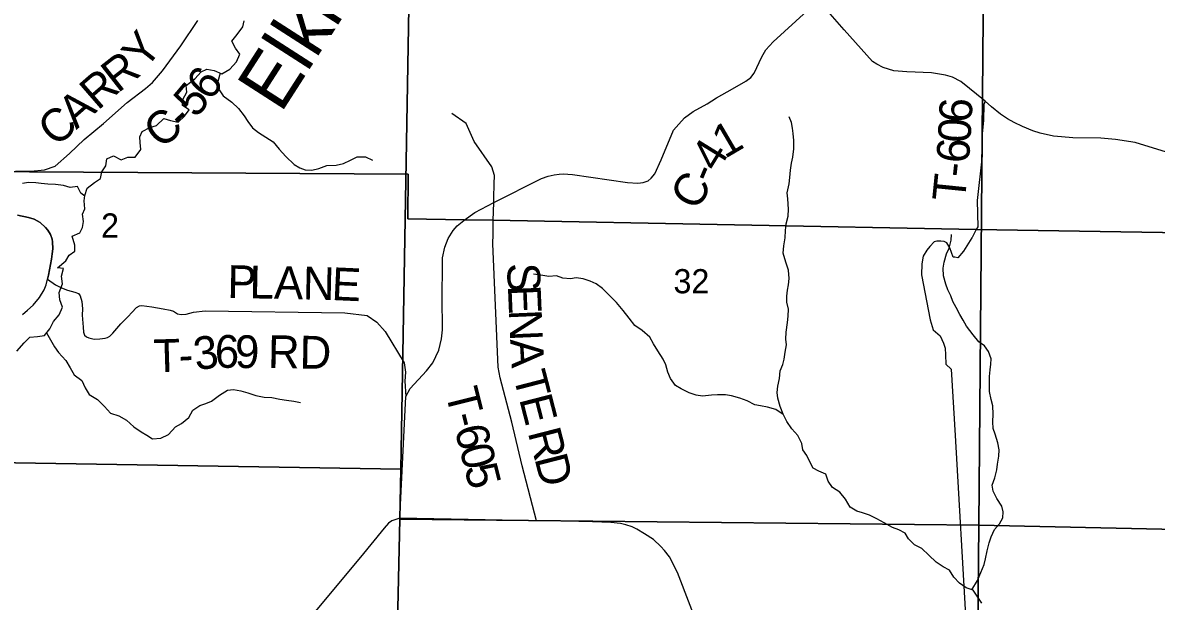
# Model space of a CAD drawing. Extents: x -3.6 to 34, y 0 to 32.8.
# Drawn here: x -0.41 to 1.556, y 29.85 to 30.853 of the extents above; entities that cross this region are included whole.
import ezdxf

# ---------------------------------------------------------------- set-up
doc = ezdxf.new("R2010")
doc.units = 0
for name, color, linetype in [('GM_X_Corporation', 7, 'Continuous'), ('GM_X_County_Road', 7, 'Continuous'), ('GM_X_County_Road_Text', 7, 'Continuous'), ('GM_X_Minor_River', 7, 'Continuous'), ('GM_X_Minor_River_Text', 7, 'Continuous'), ('GM_X_Section_Text', 7, 'Continuous'), ('GM_X_State_Route', 7, 'Continuous'), ('GM_X_Township_Road', 7, 'Continuous'), ('GM_X_Township_Road_Text', 7, 'Continuous')]:
    doc.layers.add(name, color=color, linetype=linetype)

msp = doc.modelspace()

# ---------------------------------------------------------------- linework, layer by layer
at = {"layer": 'GM_X_Corporation'}
for points in [[(3.1705, 30.458), (3.1705, 32.8429), (-3.6295, 32.8429), (-3.6295, 30.6462), (-3.5736, 30.6453), (-2.8007, 30.6338), (-2.7027, 30.634), (-2.3541, 30.6318), (-0.5034, 30.5954), (-0.453, 30.5952), (-0.398, 30.5946), (0.2583, 30.5905), (0.2578, 30.5133), (0.3556, 30.5115), (0.4055, 30.5105), (1.2437, 30.4948), (1.7819, 30.4857), (3.0419, 30.4594)], [(-0.7569, 31.1125), (0.2635, 31.0982), (0.262, 31.0128), (0.2459, 30.0789), (-0.7755, 30.0957)], [(0.262, 31.0128), (1.2573, 30.9978), (1.2483, 29.9822), (0.244, 29.9924), (0.2459, 30.0789)], [(1.2573, 30.9978), (2.27, 30.9827), (2.2535, 29.9602), (1.2483, 29.9822)], [(-0.7755, 30.0957), (0.2459, 30.0789), (0.244, 29.9924), (0.223, 29.0627), (-0.7627, 29.0764), (-0.7893, 29.0771)], [(1.2483, 29.9822), (1.2386, 28.9647), (0.2524, 28.9828), (0.2209, 28.9831), (0.223, 29.0627), (0.244, 29.9924)], [(2.2535, 29.9602), (2.2411, 28.9502), (1.4051, 28.9619), (1.2386, 28.9647), (1.2483, 29.9822)]]:
    msp.add_lwpolyline(points, close=True, dxfattribs=at)
msp.add_lwpolyline([(-2.8635, 26.0429), (2.3706, 26.0429), (2.3712, 26.0804), (2.3716, 26.1248), (2.3732, 26.2253), (2.3789, 26.6097), (2.3911, 27.5117), (2.3952, 27.9336), (2.3997, 28.282), (2.4082, 28.9473), (2.5416, 28.945), (2.5837, 28.9442), (2.8343, 28.9397), (3.1705, 28.9337), (3.1705, 30.458), (3.0419, 30.4594), (1.7819, 30.4857), (1.2437, 30.4948), (0.4055, 30.5105), (0.3556, 30.5115), (0.2578, 30.5133), (0.2583, 30.5905), (-0.398, 30.5946), (-0.453, 30.5952)], dxfattribs=at)
at = {"layer": 'GM_X_County_Road'}
for points in [[(0.3549, 30.5103), (0.3558, 30.5109), (0.3742, 30.5239), (0.4072, 30.5411), (0.4898, 30.5832), (0.5014, 30.5872), (0.5118, 30.5894), (0.5207, 30.5907), (0.5274, 30.5909), (0.5436, 30.5902), (0.639, 30.5761), (0.6567, 30.5751), (0.666, 30.5758), (0.6747, 30.579), (0.6801, 30.5836), (0.6861, 30.5913), (0.6971, 30.6153), (0.7189, 30.667), (0.7279, 30.6773), (0.7381, 30.6883), (0.7526, 30.6993), (0.777, 30.7127), (0.7935, 30.723), (0.821, 30.7385), (0.8441, 30.7516), (0.8528, 30.7582), (0.8588, 30.7657), (0.8719, 30.7941), (0.8787, 30.8061), (0.8918, 30.82), (0.9701, 30.8915)], [(-0.4222, 30.5962), (-0.3959, 30.5957), (-0.372, 30.5979), (-0.354, 30.6042), (-0.3288, 30.6261), (-0.3034, 30.6505), (-0.2697, 30.6781), (-0.229, 30.7149), (-0.1968, 30.7392), (-0.185, 30.7494), (-0.1673, 30.7695), (-0.136, 30.813), (-0.1061, 30.8567)], [(-0.3669, 30.4082), (-0.3655, 30.4152), (-0.3601, 30.4429), (-0.3589, 30.4521), (-0.358, 30.4613), (-0.3583, 30.473), (-0.359, 30.4776), (-0.3619, 30.4858), (-0.3664, 30.4937), (-0.3704, 30.498), (-0.3799, 30.5066), (-0.3903, 30.5123), (-0.4, 30.5155), (-0.4192, 30.5192)], [(0.2438, 29.994), (0.2545, 30.2049), (0.262, 30.219), (0.2905, 30.2496), (0.3013, 30.2633), (0.312, 30.2856), (0.3163, 30.3048), (0.3181, 30.3207), (0.3174, 30.3775), (0.3178, 30.4318), (0.3179, 30.4455), (0.3222, 30.4639), (0.3279, 30.4788), (0.3368, 30.4927), (0.3434, 30.5011), (0.3549, 30.5103)], [(-0.4105, 30.3472), (-0.4016, 30.3547), (-0.3918, 30.3635), (-0.3807, 30.3764), (-0.3727, 30.3901), (-0.3693, 30.3984), (-0.3669, 30.4082)], [(0.7696, 29.7854), (0.7256, 29.9001), (0.7116, 29.9268), (0.7034, 29.938), (0.697, 29.9451), (0.684, 29.9569), (0.6687, 29.967), (0.6554, 29.9748), (0.647, 29.9789), (0.6359, 29.9827), (0.6266, 29.9847), (0.6101, 29.9864), (0.5785, 29.9879), (0.5308, 29.9886), (0.481, 29.9897), (0.2438, 29.994), (0.2303, 29.9894), (0.2242, 29.9853), (0.2171, 29.9768), (0.1758, 29.9267), (0.0971, 29.8323)]]:
    msp.add_lwpolyline(points, dxfattribs=at)
at = {"layer": 'GM_X_Minor_River'}
for points in [[(-0.0779, 30.7703), (-0.0646, 30.7645), (-0.0507, 30.7727), (-0.0392, 30.7854), (-0.0337, 30.7987), (-0.0407, 30.8092), (-0.0473, 30.8209), (-0.038, 30.8324), (-0.028, 30.8458), (-0.0259, 30.8561)], [(-0.4201, 30.2834), (-0.4075, 30.298), (-0.3974, 30.308), (-0.3846, 30.309), (-0.3721, 30.3107), (-0.3632, 30.3226), (-0.3566, 30.3352), (-0.3469, 30.3464), (-0.3411, 30.3601), (-0.3458, 30.3725), (-0.3468, 30.3854), (-0.3409, 30.4003), (-0.343, 30.4139), (-0.3394, 30.4269), (-0.3497, 30.4279), (-0.3355, 30.4402), (-0.3296, 30.4502), (-0.3195, 30.4572), (-0.3196, 30.4674), (-0.324, 30.4833), (-0.3109, 30.4888), (-0.3065, 30.4983), (-0.3044, 30.5082), (-0.3064, 30.5211), (-0.3024, 30.5306), (-0.3034, 30.5443), (-0.302, 30.5538), (-0.2981, 30.5663), (-0.2857, 30.576), (-0.2749, 30.583), (-0.2728, 30.5948), (-0.2661, 30.6051), (-0.2644, 30.6173), (-0.2524, 30.6224), (-0.2394, 30.6154), (-0.2277, 30.6198), (-0.2152, 30.6199), (-0.2052, 30.6334), (-0.2062, 30.6455), (-0.2071, 30.655), (-0.2031, 30.6645), (-0.1895, 30.6715), (-0.1779, 30.6751), (-0.1652, 30.6871), (-0.1538, 30.6838), (-0.1405, 30.6806), (-0.1293, 30.691), (-0.1215, 30.7022), (-0.1326, 30.7096), (-0.1324, 30.7202), (-0.1254, 30.7325), (-0.1263, 30.7442), (-0.1114, 30.7558), (-0.1006, 30.7677), (-0.0908, 30.7728), (-0.0779, 30.7703)], [(-0.0676, 30.7658), (-0.0716, 30.7511), (-0.0702, 30.7386), (-0.0625, 30.7266), (-0.0472, 30.7154), (-0.0357, 30.7042), (-0.026, 30.6915), (-0.0198, 30.6817), (-0.0117, 30.6708), (-0.0013, 30.6627), (0.0246, 30.6464), (0.035, 30.634), (0.0466, 30.6209), (0.0608, 30.6071), (0.0704, 30.6012), (0.0799, 30.5983), (0.0916, 30.5977), (0.1037, 30.6005), (0.1176, 30.6057), (0.1335, 30.6063), (0.1463, 30.6091), (0.1587, 30.615), (0.17, 30.6205), (0.1843, 30.6207), (0.1969, 30.6149)], [(0.914, 30.3163), (0.9164, 30.3334), (0.9178, 30.3444), (0.9183, 30.3566), (0.9155, 30.3686), (0.9153, 30.3789), (0.9163, 30.3891), (0.9184, 30.3987), (0.9194, 30.4097), (0.918, 30.4241), (0.9137, 30.438), (0.9089, 30.4535), (0.9102, 30.466), (0.9127, 30.4801), (0.9132, 30.4926), (0.9142, 30.5044), (0.9174, 30.5177), (0.9183, 30.5299), (0.9173, 30.5477), (0.916, 30.5583), (0.9192, 30.5735), (0.9205, 30.5849), (0.9218, 30.5975), (0.9232, 30.6096), (0.9256, 30.6199), (0.9277, 30.6343), (0.9275, 30.6488), (0.9262, 30.6609), (0.9253, 30.6703), (0.9232, 30.6802), (0.9193, 30.69)], [(-0.3022, 30.5525), (-0.3093, 30.5578), (-0.3151, 30.5691), (-0.3276, 30.5674), (-0.3394, 30.571), (-0.353, 30.5727), (-0.3663, 30.5733), (-0.378, 30.5742), (-0.3875, 30.5752), (-0.4, 30.5762), (-0.4106, 30.5741)], [(1.236, 29.87), (1.246, 29.8859), (1.2519, 29.9), (1.2577, 29.9138), (1.2598, 29.9233), (1.263, 29.9374), (1.2662, 29.9511), (1.2698, 29.9617), (1.2753, 29.9743), (1.2843, 29.9843), (1.2898, 29.9947), (1.2907, 30.0053), (1.2883, 30.0151), (1.2798, 30.0279), (1.2732, 30.0407), (1.2715, 30.0513), (1.2762, 30.0639), (1.2798, 30.0776), (1.2808, 30.0878), (1.2832, 30.1015), (1.2838, 30.1125), (1.2814, 30.1246), (1.2766, 30.1397), (1.2734, 30.1495), (1.2728, 30.1613), (1.273, 30.1742), (1.2728, 30.189), (1.27, 30.1996), (1.2671, 30.2136), (1.2666, 30.2261), (1.2667, 30.2397), (1.2681, 30.2511), (1.2691, 30.261), (1.2697, 30.2705), (1.2649, 30.2829), (1.2584, 30.2927), (1.2484, 30.2998), (1.2388, 30.3121), (1.2268, 30.3271), (1.2213, 30.3373), (1.2155, 30.3474), (1.2089, 30.3591), (1.2031, 30.3696), (1.1995, 30.3794), (1.1948, 30.39), (1.1909, 30.3998), (1.1869, 30.4141), (1.1867, 30.4278), (1.1884, 30.438), (1.192, 30.4521), (1.1967, 30.4621), (1.2003, 30.4758), (1.2009, 30.486)], [(0.9092, 30.1739), (0.896, 30.1825), (0.882, 30.1865), (0.8698, 30.1889), (0.8596, 30.1903), (0.8466, 30.1973), (0.8336, 30.2024), (0.8196, 30.2064), (0.809, 30.2077), (0.795, 30.2079), (0.7848, 30.2074), (0.7693, 30.2056), (0.7583, 30.2073), (0.7457, 30.2113), (0.732, 30.2183), (0.7224, 30.2242), (0.7136, 30.2362), (0.7088, 30.2475), (0.7052, 30.26), (0.7009, 30.2698), (0.6913, 30.2841), (0.6843, 30.2961), (0.6776, 30.3077), (0.6642, 30.3197), (0.6516, 30.3282), (0.6416, 30.3406), (0.6315, 30.3541), (0.6196, 30.3679), (0.6088, 30.3788), (0.5954, 30.3922), (0.5847, 30.4004), (0.5744, 30.4052), (0.5618, 30.4091), (0.5501, 30.4109), (0.5403, 30.4088), (0.527, 30.4101), (0.516, 30.4141), (0.5023, 30.4132), (0.4887, 30.4152), (0.4762, 30.4173)], [(-0.3687, 30.3153), (-0.3548, 30.2912), (-0.3482, 30.2815), (-0.3355, 30.2673), (-0.3277, 30.2545), (-0.3207, 30.2428), (-0.3077, 30.2328), (-0.3015, 30.22), (-0.2949, 30.2083), (-0.2803, 30.1998), (-0.2684, 30.1879), (-0.258, 30.1763), (-0.2436, 30.1716), (-0.2302, 30.1642), (-0.2172, 30.1526), (-0.2046, 30.1437), (-0.195, 30.1378), (-0.1847, 30.1319), (-0.1703, 30.1325), (-0.1572, 30.1391), (-0.1449, 30.1522), (-0.1348, 30.1581), (-0.1221, 30.1689), (-0.1147, 30.1815), (-0.1027, 30.1893), (-0.0925, 30.1928), (-0.0828, 30.1968), (-0.0689, 30.2072), (-0.0551, 30.2162), (-0.0445, 30.2171), (-0.0316, 30.2146), (-0.0198, 30.2114), (-0.0057, 30.2067), (0.0087, 30.2039), (0.022, 30.2033), (0.036, 30.2005), (0.0474, 30.1988), (0.0603, 30.1971), (0.072, 30.1946)], [(1.2538, 29.8469), (1.2465, 29.8571), (1.2387, 29.8691), (1.2262, 29.8735), (1.2151, 29.8813), (1.2051, 29.8917), (1.1973, 29.9037), (1.1866, 29.9096), (1.1744, 29.9178), (1.1617, 29.9298), (1.1494, 29.9413), (1.1369, 29.9476), (1.1261, 29.958), (1.1203, 29.9678), (1.1096, 29.9737), (1.0986, 29.9781), (1.0844, 29.9858), (1.0715, 29.9929), (1.0589, 29.9991), (1.0463, 30.0035), (1.0368, 30.0064), (1.0254, 30.0134), (1.0168, 30.0269), (1.0072, 30.0393), (0.9946, 30.0471), (0.9872, 30.0583), (0.9832, 30.0704), (0.9707, 30.0755), (0.9611, 30.0807), (0.9549, 30.0927), (0.9502, 30.1029), (0.9432, 30.1127), (0.9416, 30.1233), (0.9345, 30.1372), (0.9241, 30.1492), (0.9153, 30.1615), (0.909, 30.1743), (0.9039, 30.1875), (0.8995, 30.2023), (0.8986, 30.2117), (0.8996, 30.2228), (0.9024, 30.2361), (0.9037, 30.2497), (0.9084, 30.2604), (0.9106, 30.27), (0.9127, 30.2821), (0.9147, 30.2947), (0.9134, 30.3045), (0.914, 30.3163)]]:
    msp.add_lwpolyline(points, dxfattribs=at)
at = {"layer": 'GM_X_State_Route'}
for points in [[(1.2591, 30.7169), (1.2173, 30.7512), (1.2028, 30.7589), (1.1903, 30.7621), (1.1664, 30.766), (1.1235, 30.7677), (1.1008, 30.7698), (1.0827, 30.7752), (1.0717, 30.7812), (1.0639, 30.7856), (1.0145, 30.8408), (0.9701, 30.8915)], [(1.5736, 30.6285), (1.5197, 30.6456), (1.4856, 30.6508), (1.46, 30.6527), (1.4112, 30.6537), (1.3917, 30.6555), (1.378, 30.6566), (1.3547, 30.6615), (1.342, 30.6656), (1.3239, 30.6729), (1.3095, 30.6799), (1.2981, 30.6862), (1.2858, 30.6947), (1.2703, 30.7072), (1.2591, 30.7169)]]:
    msp.add_lwpolyline(points, dxfattribs=at)
at = {"layer": 'GM_X_Township_Road'}
msp.add_line((1.2071, 30.1375), (1.2419, 29.5394), dxfattribs=at)
for points in [[(1.2591, 30.7169), (1.257, 30.7114), (1.2564, 30.6837), (1.2537, 30.6544), (1.2541, 30.6225), (1.2453, 30.5449), (1.2464, 30.499), (1.2439, 30.4943), (1.2369, 30.4809), (1.2364, 30.48), (1.2215, 30.457), (1.2119, 30.4457), (1.2065, 30.4464)], [(0.4073, 30.5493), (0.4077, 30.5736), (0.408, 30.5882), (0.4034, 30.6031), (0.373, 30.6472), (0.3593, 30.6784), (0.3345, 30.6959)], [(0.4057, 30.509), (0.4057, 30.51), (0.4072, 30.5411), (0.4073, 30.5493)], [(-0.4192, 30.5192), (-0.4, 30.5155), (-0.3903, 30.5123), (-0.3799, 30.5066), (-0.3704, 30.498), (-0.3664, 30.4937), (-0.3619, 30.4858), (-0.359, 30.4776), (-0.3583, 30.473), (-0.358, 30.4613), (-0.3589, 30.4521), (-0.3601, 30.4429), (-0.3655, 30.4152), (-0.3669, 30.4082)], [(0.481, 29.9897), (0.4563, 30.0848), (0.4383, 30.1608), (0.4181, 30.2373), (0.4147, 30.2556), (0.4052, 30.4699), (0.4057, 30.4865), (0.4057, 30.509)], [(1.2065, 30.4464), (1.2039, 30.4467), (1.1978, 30.4625), (1.1926, 30.4715), (1.188, 30.4735), (1.1826, 30.4746), (1.1755, 30.4741), (1.1709, 30.4729), (1.1635, 30.4652), (1.1579, 30.4586), (1.1517, 30.4486), (1.1497, 30.4348), (1.1491, 30.4158), (1.1638, 30.3382), (1.1691, 30.3205), (1.1812, 30.3101), (1.1872, 30.2977), (1.1897, 30.2886), (1.1903, 30.2773), (1.1914, 30.2613), (1.2004, 30.2524), (1.2071, 30.1375)], [(-0.3669, 30.4082), (-0.3531, 30.3986), (-0.3425, 30.3933), (-0.3323, 30.3893), (-0.3198, 30.3861), (-0.3135, 30.3838), (-0.3102, 30.3798), (-0.3076, 30.3695), (-0.3066, 30.3569), (-0.3069, 30.3461), (-0.3054, 30.3255), (-0.3045, 30.3166), (-0.3026, 30.3111), (-0.2996, 30.3084), (-0.2954, 30.3069), (-0.2861, 30.3045), (-0.2764, 30.3048), (-0.2671, 30.3059), (-0.2627, 30.3071), (-0.2591, 30.3096), (-0.2536, 30.3151), (-0.2401, 30.3311), (-0.2272, 30.3438), (-0.221, 30.3508), (-0.2126, 30.3595), (-0.2075, 30.362), (-0.2033, 30.3628), (-0.186, 30.3607), (-0.1666, 30.3569), (-0.1541, 30.3546), (-0.1485, 30.3529), (-0.1417, 30.3484), (-0.1353, 30.3472), (-0.1264, 30.3477), (-0.1136, 30.3511), (-0.0935, 30.3538), (0.1485, 30.3499), (0.1872, 30.3454), (0.2041, 30.334), (0.2189, 30.3175), (0.2515, 30.2633), (0.2538, 30.2473), (0.2527, 30.2318), (0.2545, 30.2049)]]:
    msp.add_lwpolyline(points, dxfattribs=at)

# ---------------------------------------------------------------- texts
at = {"layer": 'GM_X_County_Road_Text'}
for s, rotation, p in [('Y', 51.9226, (-0.1978, 30.7694)), ('R', 38.0573, (-0.2451, 30.73)), ('6', 52.9164, (-0.0851, 30.7154)), ('R', 40.984, (-0.2798, 30.6999)), ('5', 49.963, (-0.1096, 30.6861)), ('A', 41.4573, (-0.3171, 30.6669)), ('C', 41.4639, (-0.3521, 30.636)), ('C', 40.2103, (-0.1698, 30.6326)), ('-', 42.8991, (-0.132, 30.6646)), ('1', 30.3403, (0.8076, 30.6166)), ('4', 58.3396, (0.7944, 30.5919)), ('-', 67.0388, (0.7863, 30.5724)), ('C', 59.5212, (0.759, 30.525))]:
    msp.add_text(s, height=0.0568, rotation=rotation, dxfattribs=at).set_placement(p)
at = {"layer": 'GM_X_Minor_River_Text'}
msp.add_text('Elkhorn', height=0.09469, rotation=57.285, dxfattribs=at).set_placement((0.0375, 30.6945))
at = {"layer": 'GM_X_Section_Text'}
for s, height, p in [('2', 0.0419, (-0.2742, 30.4806)), ('32', 0.04186, (0.7187, 30.384))]:
    msp.add_text(s, height=height, rotation=0, dxfattribs=at).set_placement(p)
at = {"layer": 'GM_X_Township_Road_Text'}
for s, height, rotation, p in [('6', 0.0568, 86.9542, (1.2356, 30.679)), ('0', 0.0568, 86.6434, (1.2336, 30.644)), ('6', 0.0568, 85.4958, (1.2308, 30.6082)), ('-', 0.0568, 83.8131, (1.2281, 30.5834)), ('T', 0.0568, 84.2374, (1.2239, 30.5413)), ('P', 0.0568, 358.8311, (-0.0554, 30.3761)), ('L', 0.0568, 358.8321, (-0.0171, 30.3753)), ('A', 0.0568, 358.8306, (0.0254, 30.3745)), ('N', 0.0568, 358.7595, (0.0754, 30.3734)), ('E', 0.0568, 357.3891, (0.125, 30.3724)), ('S', 0.0568, 272.3954, (0.4298, 30.4357)), ('E', 0.0568, 272.3982, (0.4314, 30.3974)), ('N', 0.0568, 272.4002, (0.4332, 30.355)), ('T', 0.0568, 1.7424, (-0.1822, 30.247)), ('3', 0.0568, 8.1555, (-0.1095, 30.2502)), ('6', 0.0568, 359.3339, (-0.0771, 30.255)), ('9', 0.0568, 359.2012, (-0.0422, 30.2546)), ('RD', 0.05682, 359.0118, (0.015, 30.2546)), ('A', 0.0568, 273.2783, (0.4353, 30.304)), ('-', 0.0568, 3.0413, (-0.1383, 30.2484)), ('T', 0.0568, 284.521, (0.4401, 30.2421)), ('T', 0.0568, 284.0888, (0.3225, 30.2129)), ('E', 0.0568, 284.4229, (0.4507, 30.201)), ('-', 0.0568, 284.099, (0.3328, 30.1718)), ('6', 0.0568, 284.1255, (0.3385, 30.1493)), ('R', 0.0568, 284.4291, (0.4657, 30.1429)), ('0', 0.0568, 284.1938, (0.347, 30.1156)), ('D', 0.0568, 284.4281, (0.4773, 30.0977)), ('5', 0.0568, 284.2607, (0.3555, 30.0818))]:
    msp.add_text(s, height=height, rotation=rotation, dxfattribs=at).set_placement(p)

doc.saveas('drawing.dxf')
